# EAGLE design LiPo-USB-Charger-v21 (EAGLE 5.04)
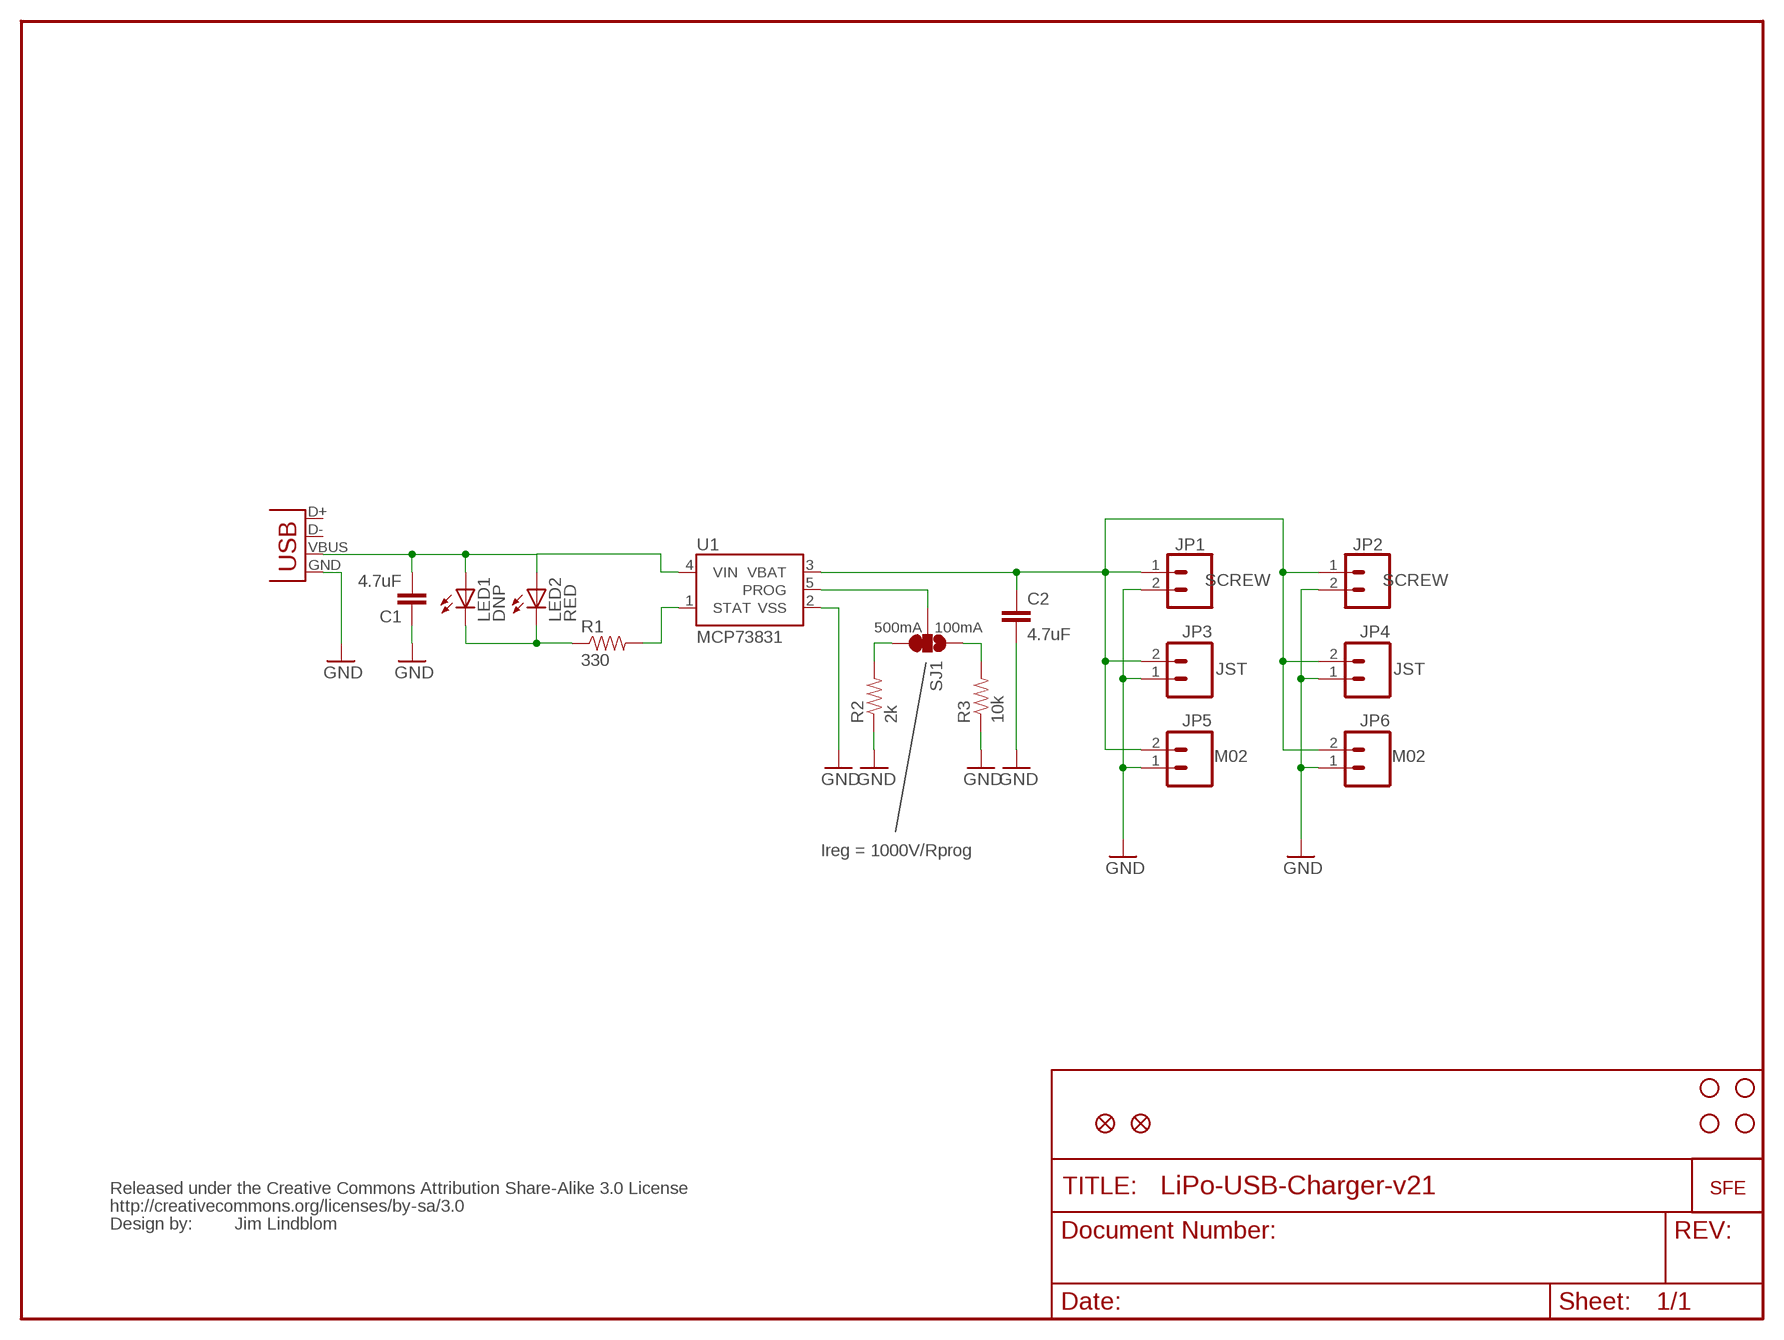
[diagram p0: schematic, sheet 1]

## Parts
C1  4.7uF  CAP0402-CAP  [0402-CAP]
C2  4.7uF  CAP0402-CAP  [0402-CAP]
JP1  SCREW  M023.5MM-NO_SILK  [SCREWTERMINAL-3.5MM-2-NS]
JP2  SCREW  M023.5MM-NO_SILK  [SCREWTERMINAL-3.5MM-2-NS]
JP3  JST  M02JST-PTH-2  [JST-2-PTH]
JP4  JST  M02JST-PTH-2  [JST-2-PTH]
JP5  M02  M02PTH  [1X02]
JP6  M02  M02PTH  [1X02]
JP7  STAND-OFF  [STAND-OFF]
JP8  STAND-OFF  [STAND-OFF]
JP9  STAND-OFF  [STAND-OFF]
JP10  STAND-OFF  [STAND-OFF]
JP11  LOGO-SFENEW  [SFE-NEW-WEBLOGO]
JP12  FIDUCIAL1X2  [FIDUCIAL-1X2]
JP13  FIDUCIAL1X2  [FIDUCIAL-1X2]
LED1  DNP  LED3MM  [LED3MM]
LED2  RED  LED0603  [LED-0603]
R1  330  RESISTOR0402-RES  [0402-RES]
R2  2k  RESISTOR0402-RES  [0402-RES]
R3  10k  RESISTOR0402-RES  [0402-RES]
SJ1  SOLDERJUMPER_2WAYS  [SJ_3]
U1  MCP73831  [SOT23-5]
U$  CREATIVE_COMMONS  [CREATIVE_COMMONS]
X1  USBSMD  [USB-MINIB]

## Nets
GND: C1.1 C2.2 JP1.2 JP2.2 JP3.1 JP4.1 JP5.1 JP6.1 R2.1 R3.1 U1.2(VSS) X1.GND
N$1: C1.2 LED1.A LED2.A U1.4(VIN) X1.VBUS
N$2: R1.2 U1.1(STAT)
N$3: LED1.K(C) LED2.C R1.1
N$4: R2.2 SJ1.3
N$7: R3.2 SJ1.1
PROG: SJ1.2 U1.5(PROG)
VBAT: C2.1 JP1.1 JP2.1 JP3.2 JP4.2 JP5.2 JP6.2 U1.3(VBAT)
Unconnected: X1.D+ X1.D-

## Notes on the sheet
- 500mA | 100mA
- Ireg = 1000V/Rprog
- Jim Lindblom

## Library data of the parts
C1 C2 = SparkFun:CAP: Capacitor
JP1-JP6 = SparkFun:M02: Header 2
JP7-JP10 = SparkFun:STAND-OFF: Stand Off
JP11 = SparkFun:LOGO-SFE: Spark Fun Electronics PCB Logo
JP12 JP13 = SparkFun:FIDUCIAL: Fiducial Alignment Points
LED1 LED2 = SparkFun:LED: LEDs
R1-R3 = SparkFun:RESISTOR: Resistor
SJ1 = SparkFun:SOLDERJUMPER_2WAY: Solder Jumper 2 way solder jumper
U1 = SparkFun:MCP73831: Microchip's MCP73831 Miniature single cell, fully integrated Li-Ion, Li-polymer charge management controller http://ww1.microchip.com/downloads/en/DeviceDoc/21984a.pdf
U$ = SparkFun:CREATIVE_COMMONS
X1 = SparkFun:USB: USB Connectors USB-B-PTH is fully proven SKU : PRT-00139 USB-miniB is fully proven SKU : PRT-00587 USB-A-PCB is untested. USB-A-H is throughly reviewed, but untested. Spark Fun Electronics SKU : PRT-00437 USB-B-SMT is throughly reviewed, but untested. Needs silkscreen touching up. USB-A-S has not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

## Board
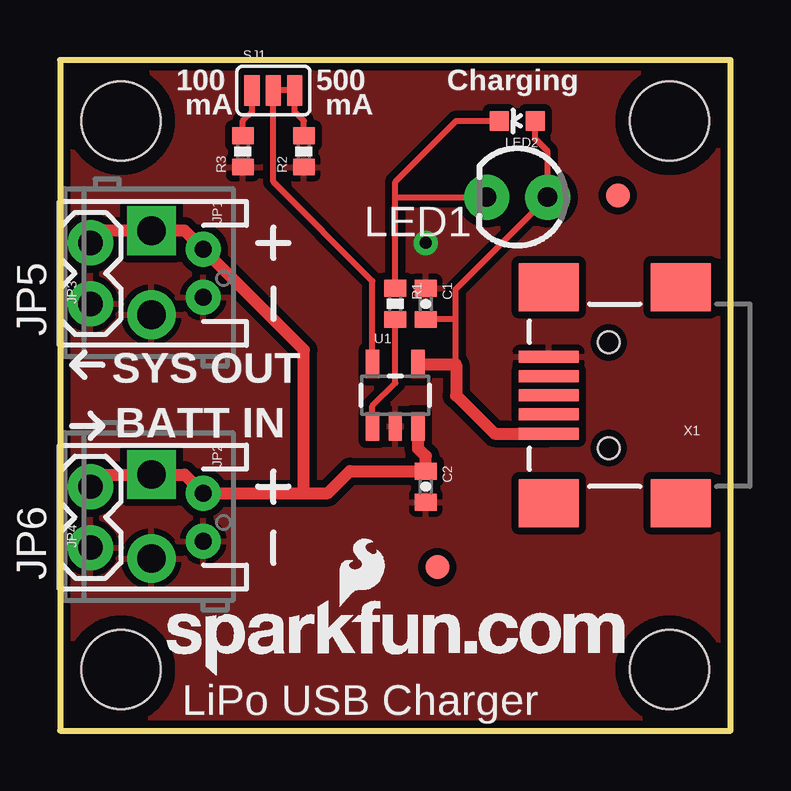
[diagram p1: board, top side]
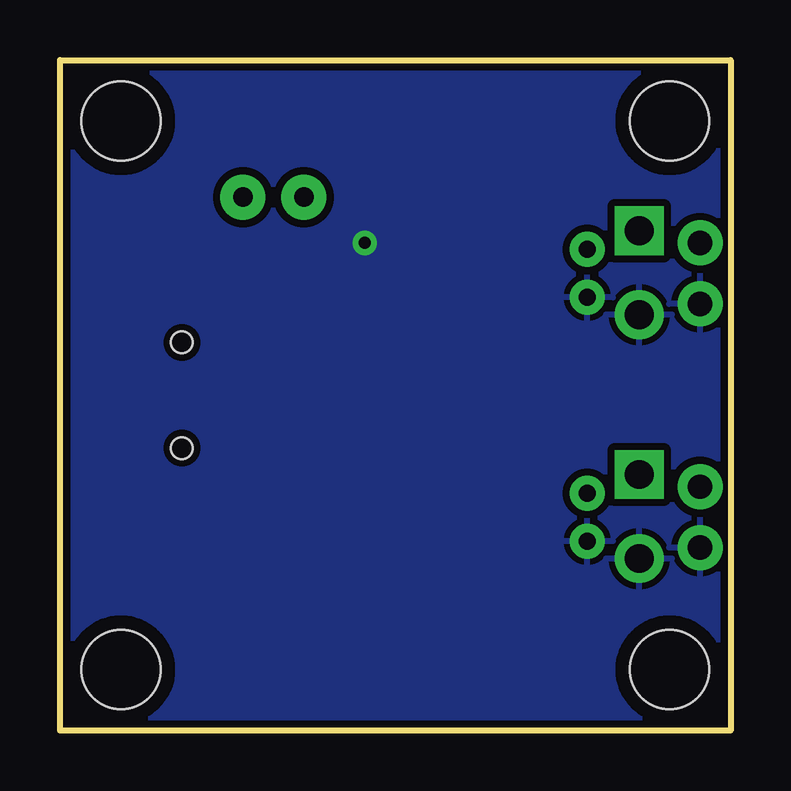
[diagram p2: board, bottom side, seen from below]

Size 27.94 x 27.94 mm. Coordinates in mm from the lower left corner, seen from the top.
Outline: 0,0 27.94,0 27.94,27.94 0,27.94 0,0
Copper layers (1*16): Top 0.035mm / dielectric 1.5mm / Bottom 0.035mm
Design rules "SparkFun *": minimum track width 8mil, minimum drill 20mil, track to track 8mil, track to pad 8mil, pad to pad 8mil, via to via 8mil, smd to smd 8mil, copper to edge 8mil, drill to drill 8mil, minimum pad ring 12mil, minimum via ring 10mil, stop-mask expansion 4mil, vias tented up to drill 20mil, thermal gap 10mil

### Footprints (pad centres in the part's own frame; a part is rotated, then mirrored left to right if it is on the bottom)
0402-CAP = smd 0.7 x 0.9: 1 -0.65,0; 2 0.65,0
SCREWTERMINAL-3.5MM-2-NS = drill 1.2 pad 2.032 square: 1 0,0 | drill 1.2 pad 2.032 round: 2 3.5,0
JST-2-PTH = drill 0.7 pad 1.448 round: 1 -1,0; 2 1,0
1X02 = drill 1.016 pad 1.88 round: 1 0,0; 2 2.54,0
STAND-OFF = hole 3.302: 0,0
FIDUCIAL-1X2 = smd 1 x 1: 1 0,0
LED3MM = drill 0.813 pad 1.88 round: A -1.27,0; K 1.27,0
LED-0603 = smd 0.8 x 0.8: A 0,-0.75; C 0,0.75
0402-RES = smd 0.7 x 0.9: 1 -0.65,0; 2 0.65,0
SJ_3 = smd 0.635 x 1.27: 1 -0.889,0; 2 0,0; 3 0.889,0
SOT23-5 = smd 0.55 x 1.2: 1 -0.95,-1.3; 2 0,-1.3; 3 0.95,-1.3; 4 0.95,1.3; 5 -0.95,1.3
USB-MINIB = smd 2.5 x 0.5: D+ 2.5,0; D- 2.5,0.8; GND 2.5,-1.6; ID 2.5,-0.8; VBUS 2.5,1.6 | smd 2.5 x 2: MTN1 -3,4.5; MTN2 2.5,4.5; MTN3 -3,-4.5; MTN4 2.5,-4.5 | hole 0.9: 0,2.2; 0,-2.2

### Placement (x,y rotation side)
C1  15.24,17.78 270 top
C2  15.24,10.16 270 top
JP1  3.81,20.83 270 top
JP2  3.81,10.67 270 top
JP3  5.97,19.05 90 top
JP4  5.97,8.89 90 top
JP5  1.27,17.78 90 top
JP6  1.27,7.62 90 top
JP7  25.4,2.54 0 top
JP8  2.54,25.4 0 top
JP9  2.54,2.54 0 top
JP10  25.4,25.4 0 top
JP11  4.45,2.29 0 top
JP12  15.72,6.81 0 top
JP13  23.24,22.3 0 top
LED1  19.05,22.23 180 top
LED2  19.05,25.4 90 top
R1  13.97,17.78 270 top
R2  10.16,24.13 90 top
R3  7.62,24.13 90 top
SJ1  8.89,26.67 0 top
U1  13.97,13.97 0 top
U$  0,-2.54 0 top
X1  22.86,13.97 180 top

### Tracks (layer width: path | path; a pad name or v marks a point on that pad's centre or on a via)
GND  (via drill 0.51)
  other vias: 15.24,20.32
  pour Bottom (isolate 0.305): 0,0 0,27.94 27.94,27.94 27.94,0
  pour Top (isolate 0.305): 0,0 0,27.94 27.94,27.94 27.94,0
N$1
  Top 0.254: 16.48,15.27 16.48,17.14 | 16.48,17.14 16.48,18.39 LED1.A 20.32,24.13 19.8,24.65 LED2.A | C1.2 16.46,17.13 16.48,17.14
  Top 0.508: X1.VBUS 18.11,12.37 16.51,13.97 16.51,15.24 16.48,15.27 U1.4
N$2
  Top 0.254: U1.1 13.02,13.53 13.97,14.48 R1.2
N$3
  Top 0.254: R1.1 13.97,22.23 | 13.97,22.23 13.97,22.86 16.51,25.4 LED2.C | 13.97,22.23 LED1.K
N$4
  Top 0.254: R2.2 10.16,25.4 9.78,25.78 SJ1.3
N$5
  Top 0.254: 9.91,26.67 8.76,26.67
N$7
  Top 0.254: R3.2 7.62,25.4 8,25.78 SJ1.1
PROG
  Top 0.254: SJ1.2 8.89,22.86 13.02,18.73 U1.5
VBAT
  Top 0.508: 10.16,9.89 JP4.2 5.19,10.67 JP2.1 1.78,10.67 JP6.2 | 10.16,9.89 11.16,9.89 12.08,10.81 C2.1 15.24,11.43 14.92,11.75 U1.3 | JP5.2 1.78,20.83 JP1.1 5.19,20.83 JP3.2 10.16,15.86 10.16,9.89

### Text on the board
tPlace: 100 | 500 | Charging | mA | mA | SYS OUT | BATT IN | LiPo USB Charger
